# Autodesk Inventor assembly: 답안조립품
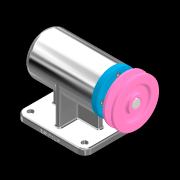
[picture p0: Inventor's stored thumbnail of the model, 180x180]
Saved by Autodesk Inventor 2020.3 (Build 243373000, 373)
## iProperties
Created: 2020-10
Part Number: 답안조립품
Document SubType Name: Assembly
Designer: EZDESIGN
Author: EZDESIGN
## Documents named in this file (12)
- C:\Users\EZDESIGN\Desktop\701004V1035\답안조립품.iam
- C:\Users\EZDESIGN\Desktop\701004V1035\V벨트풀리.ipt
- C:\Users\EZDESIGN\Desktop\701004V1035\멈춤나사 M3.ipt
- C:\Users\EZDESIGN\Desktop\701004V1035\베어링 51202.ipt
- C:\Users\EZDESIGN\Desktop\701004V1035\베어링 6004.ipt
- C:\Users\EZDESIGN\Desktop\701004V1035\본체.ipt
- C:\Users\EZDESIGN\Desktop\701004V1035\볼트 M4.ipt
- C:\Users\EZDESIGN\Desktop\701004V1035\어댑터슬리브.ipt
- C:\Users\EZDESIGN\Desktop\701004V1035\오일 실.ipt
- C:\Users\EZDESIGN\Desktop\701004V1035\축.ipt
- C:\Users\EZDESIGN\Desktop\701004V1035\커버.ipt
- C:\Users\EZDESIGN\Desktop\701004V1035\키 5 x 5 x 16.ipt
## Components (1 placed, 1 different names)
1. V벨트풀리:1
